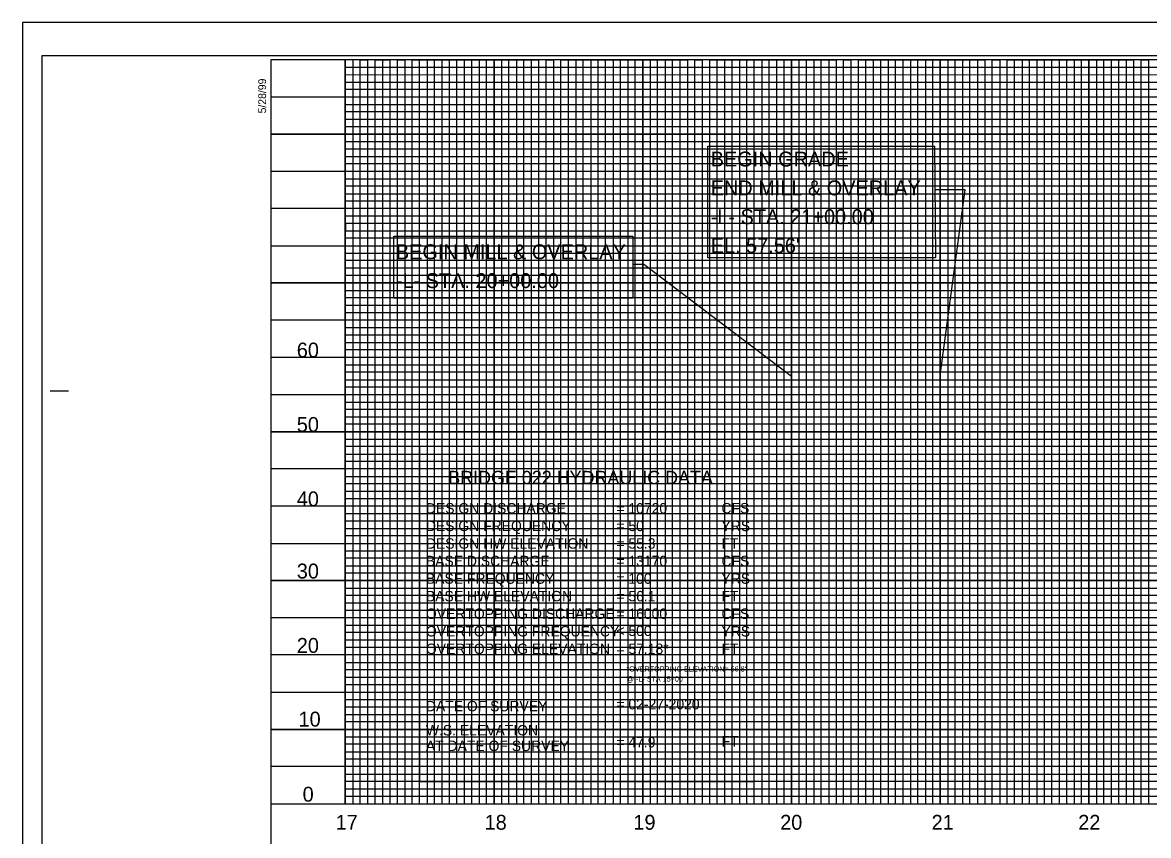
# Model space of a CAD drawing. Extents: x 1019474 to 1021161, y 504129 to 505324.
# Drawn here: x 1019474 to 1020231, y 504683 to 505229 of the extents above; entities that cross this region are included whole.
import ezdxf

# ---------------------------------------------------------------- set-up
doc = ezdxf.new("R2010")
doc.units = 0
for name, color, linetype in [('Exist Vertical Profile Horizontal Axis Label Major', 7, 'Continuous'), ('Exist Vertical Profile Vertical Axis Label', 7, 'Continuous'), ('Prop Grid Mask', 7, 'Continuous'), ('Prop Roadway Bridge', 7, 'Continuous'), ('Prop Vertical Profile Grade Label', 7, 'Continuous'), ('Sheet Cutting Line CELL', 7, 'Continuous'), ('Sheet DOT Grid CELL', 7, 'Continuous'), ('Sheet Layout Profile Border Port 1', 7, 'Continuous'), ('Sheet Plot Border Inside CELL', 7, 'Continuous'), ('Sheet Plot Border Outside CELL', 7, 'Continuous'), ('Sheet Profile CELL', 7, 'Continuous'), ('Sheet Profile Grid Major CELL', 7, 'Continuous'), ('Sheet Profile Grid Middle CELL', 7, 'Continuous'), ('Sheet Profile Grid Minor CELL', 7, 'Continuous')]:
    doc.layers.add(name, color=color, linetype=linetype)

msp = doc.modelspace()

# ---------------------------------------------------------------- linework, layer by layer
at = {"layer": 'Prop Grid Mask'}
for points in [[(1019934.88, 505146.12), (1020087.38, 505146.24), (1020088.08, 505071.15), (1019934.86, 505071.1)], [(1019723.82, 505085.77), (1019884.45, 505085.77), (1019884.45, 505043.97), (1019723.82, 505043.97)], [(1019741.22, 504719.29), (1019966.22, 504719.29), (1019966.22, 504944.29), (1019741.22, 504944.29)]]:
    msp.add_lwpolyline(points, close=True, dxfattribs=at)
at = {"layer": 'Prop Vertical Profile Grade Label'}
for p, q in [((1020107.91, 505116.78), (1020087.38, 505116.78)), ((1020091.22, 504992.18), (1020107.91, 505116.78)), ((1019891.96, 505066.68), (1019884.45, 505066.68)), ((1019991.11, 504991.32), (1019891.96, 505066.68)), ((1019891.96, 505066.68), (1019891.96, 505066.68))]:
    msp.add_line(p, q, dxfattribs=at)
at = {"layer": 'Sheet Cutting Line CELL'}
for p, q in [((1021158.22, 505229.29), (1019474.22, 505229.29)), ((1019474.22, 505229.29), (1019474.22, 504129.29))]:
    msp.add_line(p, q, dxfattribs=at)
at = {"layer": 'Sheet DOT Grid CELL'}
for p, q in [((1019691.22, 504704.29), (1019691.22, 505204.29)), ((1019741.22, 504704.29), (1019741.22, 505204.29)), ((1019791.22, 504704.29), (1019791.22, 505204.29)), ((1019841.22, 504704.29), (1019841.22, 505204.29)), ((1019891.22, 504704.29), (1019891.22, 505204.29)), ((1019941.22, 504704.29), (1019941.22, 505204.29)), ((1019991.22, 504704.29), (1019991.22, 505204.29)), ((1020041.22, 504704.29), (1020041.22, 505204.29)), ((1020091.22, 504704.29), (1020091.22, 505204.29)), ((1020141.22, 504704.29), (1020141.22, 505204.29)), ((1020191.22, 504704.29), (1020191.22, 505204.29)), ((1020941.17, 505154.29), (1019641.22, 505154.29)), ((1020941.17, 505104.29), (1019641.22, 505104.29)), ((1020941.22, 505054.29), (1019641.22, 505054.29)), ((1021141.22, 505004.29), (1019641.22, 505004.29)), ((1021141.22, 504954.29), (1019641.22, 504954.29)), ((1021141.22, 504904.29), (1019641.22, 504904.29)), ((1021141.22, 504854.29), (1019641.22, 504854.29)), ((1021141.22, 504804.29), (1019641.22, 504804.29)), ((1021141.22, 504754.29), (1019641.22, 504754.29))]:
    msp.add_line(p, q, dxfattribs=at)
at = {"layer": 'Sheet Layout Profile Border Port 1'}
msp.add_lwpolyline([(1019691.22, 505043.24), (1019691.22, 504704.29), (1021091.22, 504704.29), (1021091.22, 505043.24)], dxfattribs=at)
at = {"layer": 'Sheet Plot Border Inside CELL'}
msp.add_lwpolyline([(1019487.22, 504151.74), (1021153.72, 504151.74), (1021153.72, 505206.84), (1019487.22, 505206.84)], close=True, dxfattribs=at)
at = {"layer": 'Sheet Plot Border Outside CELL'}
msp.add_lwpolyline([(1019474.22, 504129.29), (1021158.22, 504129.29), (1021158.22, 505229.29), (1019474.22, 505229.29)], close=True, dxfattribs=at)
at = {"layer": 'Sheet Profile CELL'}
for p, q in [((1019492.72, 504981.79), (1019505.22, 504981.79)), ((1019641.22, 504704.29), (1021141.22, 504704.29))]:
    msp.add_line(p, q, dxfattribs=at)
msp.add_lwpolyline([(1021141.22, 505204.29), (1019641.22, 505204.29), (1019641.22, 504154.29), (1021141.22, 504154.29)], close=True, dxfattribs=at)
at = {"layer": 'Sheet Profile Grid Major CELL'}
for points in [[(1019691.22, 505204.29), (1019691.22, 504704.29), (1019741.22, 504704.29), (1019741.22, 505204.29), (1019791.22, 505204.29), (1019791.22, 504704.29), (1019841.22, 504704.29), (1019841.22, 505204.29), (1019891.22, 505204.29), (1019891.22, 504704.29), (1019941.22, 504704.29), (1019941.22, 505204.29), (1019991.22, 505204.29), (1019991.22, 504704.29), (1020041.22, 504704.29), (1020041.22, 505204.29), (1020091.22, 505204.29), (1020091.22, 504704.29), (1020141.22, 504704.29), (1020141.22, 505204.29), (1020191.22, 505204.29), (1020191.22, 504704.29), (1020241.22, 504704.29)], [(1019641.22, 505154.29), (1020941.22, 505154.29)], [(1020941.22, 505104.29), (1019641.22, 505104.29), (1019641.22, 505054.29), (1020941.22, 505054.29)], [(1021141.22, 505004.29), (1019641.22, 505004.29), (1019641.22, 504954.29), (1021141.22, 504954.29)], [(1021141.22, 504904.29), (1019641.22, 504904.29), (1019641.22, 504854.29), (1021141.22, 504854.29)], [(1021141.22, 504804.29), (1019641.22, 504804.29), (1019641.22, 504804.29), (1019641.22, 504754.29), (1021141.22, 504754.29)]]:
    msp.add_lwpolyline(points, dxfattribs=at)
at = {"layer": 'Sheet Profile Grid Middle CELL'}
msp.add_line((1019641.22, 505179.29), (1020941.17, 505179.29), dxfattribs=at)
for points in [[(1019716.22, 505204.29), (1019716.22, 504704.29), (1019766.22, 504704.29), (1019766.22, 505204.29), (1019816.22, 505204.29), (1019816.22, 504704.29), (1019866.22, 504704.29), (1019866.22, 505204.29), (1019916.22, 505204.29), (1019916.22, 504704.29), (1019966.22, 504704.29), (1019966.22, 505204.29), (1020016.22, 505204.29), (1020016.22, 504704.29), (1020066.22, 504704.29), (1020066.22, 505204.29), (1020116.22, 505204.29), (1020116.22, 504704.29), (1020166.22, 504704.29), (1020166.22, 505204.29), (1020216.22, 505204.29), (1020216.22, 504704.29), (1020266.22, 504704.29)], [(1020941.22, 505129.29), (1019641.22, 505129.29), (1019641.22, 505079.29), (1020941.22, 505079.29)], [(1021141.22, 505029.29), (1019641.22, 505029.29), (1019641.22, 504979.29), (1020966.22, 504979.29)], [(1021141.22, 504929.29), (1019641.22, 504929.29), (1019641.22, 504879.29), (1021141.22, 504879.29)], [(1021141.22, 504829.29), (1019641.22, 504829.29), (1019641.22, 504779.29), (1021141.22, 504779.29)], [(1021141.22, 504729.29), (1019641.22, 504729.29)]]:
    msp.add_lwpolyline(points, dxfattribs=at)
at = {"layer": 'Sheet Profile Grid Minor CELL'}
for p, q in [((1019691.22, 505199.29), (1020941.22, 505199.29)), ((1019691.22, 505194.29), (1019691.22, 505194.29)), ((1020941.22, 505194.29), (1019691.22, 505193.94)), ((1019691.22, 505189.29), (1020941.22, 505189.29)), ((1020941.17, 505069.29), (1019691.22, 505069.29)), ((1020941.22, 505064.29), (1019691.22, 505064.29)), ((1020941.22, 505059.29), (1019691.22, 505059.29)), ((1019691.22, 505049.29), (1020941.22, 505049.29)), ((1020941.22, 505044.29), (1019691.22, 505044.29)), ((1019691.22, 505039.29), (1021091.22, 505039.29)), ((1021091.22, 505019.29), (1019691.22, 505019.29)), ((1019691.22, 505014.29), (1021091.22, 505014.29)), ((1021091.22, 504994.29), (1019691.22, 504994.29)), ((1019691.22, 504989.29), (1021091.22, 504989.29)), ((1021091.22, 504969.29), (1019691.22, 504969.29)), ((1019691.22, 504964.29), (1021091.22, 504964.29)), ((1021091.22, 504959.29), (1019691.22, 504959.29)), ((1019691.22, 504949.29), (1021091.22, 504949.29)), ((1021091.22, 504944.29), (1019691.22, 504944.29)), ((1019691.22, 504939.29), (1021091.22, 504939.29)), ((1021091.22, 504934.29), (1019691.22, 504934.29)), ((1019691.22, 504924.29), (1021091.22, 504924.29)), ((1021091.22, 504919.29), (1019691.22, 504919.29)), ((1019691.22, 504914.29), (1021091.22, 504914.29)), ((1021091.22, 504909.29), (1019691.22, 504909.29)), ((1019691.22, 504899.29), (1021091.22, 504899.29)), ((1021091.22, 504894.29), (1019691.22, 504894.29)), ((1019691.22, 504889.29), (1021091.22, 504889.29)), ((1021091.22, 504884.29), (1019691.22, 504884.29)), ((1019691.22, 504874.29), (1021091.22, 504874.29)), ((1021091.22, 504869.29), (1019691.22, 504869.29)), ((1019691.22, 504864.29), (1021091.22, 504864.29)), ((1021091.22, 504859.29), (1019691.22, 504859.29)), ((1019691.22, 504849.29), (1021091.22, 504849.29)), ((1021091.22, 504844.29), (1019691.22, 504844.29)), ((1019691.22, 504839.29), (1021091.22, 504839.29)), ((1021091.22, 504834.29), (1019691.22, 504834.29)), ((1019691.22, 504824.29), (1021091.22, 504824.29)), ((1021091.22, 504819.29), (1019691.22, 504819.29)), ((1021091.22, 504814.29), (1019691.22, 504814.29)), ((1021091.22, 504809.29), (1019691.22, 504809.29)), ((1019691.22, 504799.29), (1021091.22, 504799.29)), ((1021091.22, 504794.29), (1019691.22, 504794.29)), ((1019691.22, 504789.29), (1021091.22, 504789.29)), ((1021091.22, 504784.29), (1019691.22, 504784.29)), ((1019691.22, 504774.29), (1021091.22, 504774.29)), ((1021091.22, 504769.29), (1019691.22, 504769.29)), ((1019691.22, 504764.29), (1021091.22, 504764.29)), ((1021091.22, 504759.29), (1019691.22, 504759.29)), ((1019691.22, 504749.29), (1021091.22, 504749.29)), ((1021091.22, 504744.29), (1019691.22, 504744.29)), ((1019691.22, 504739.29), (1021091.22, 504739.29)), ((1021091.22, 504734.29), (1019691.22, 504734.29)), ((1019691.22, 504724.29), (1021091.22, 504724.29)), ((1021091.22, 504719.29), (1019691.22, 504719.29)), ((1019691.22, 504714.29), (1021091.22, 504714.29))]:
    msp.add_line(p, q, dxfattribs=at)
for points in [[(1019696.22, 505204.29), (1019696.22, 504704.29), (1019701.22, 504704.29), (1019701.22, 505204.29), (1019706.22, 505204.29), (1019706.22, 504704.29), (1019711.22, 504704.29), (1019711.22, 505204.29), (1019721.22, 505204.29), (1019721.22, 504704.29), (1019726.22, 504704.29), (1019726.22, 505204.29), (1019731.22, 505204.29), (1019731.22, 504704.29), (1019736.22, 504704.29), (1019746.22, 504704.29), (1019751.22, 504704.29), (1019751.22, 505204.29), (1019756.22, 505204.29), (1019756.22, 504704.29), (1019761.22, 504704.29), (1019761.22, 505204.29), (1019771.22, 505204.29), (1019771.22, 504704.29), (1019776.22, 504704.29), (1019776.22, 505204.29), (1019781.22, 505204.29), (1019781.22, 504704.29), (1019786.22, 504704.29), (1019786.22, 505204.29), (1019796.22, 505204.29), (1019796.22, 504704.29), (1019801.22, 504704.29), (1019801.22, 505204.29), (1019806.22, 505204.29), (1019806.22, 504704.29), (1019811.22, 504704.29), (1019811.22, 505204.29), (1019821.22, 505204.29), (1019821.22, 504704.29), (1019826.22, 504704.29), (1019826.22, 505204.29), (1019831.22, 505204.29), (1019831.22, 504704.29), (1019836.22, 504704.29), (1019836.22, 505204.29), (1019846.22, 505204.29), (1019846.22, 504704.29), (1019851.22, 504704.29), (1019851.22, 505204.29), (1019856.22, 505204.29), (1019856.22, 504704.29), (1019861.22, 504704.29), (1019861.22, 505204.29), (1019871.22, 505204.29), (1019871.22, 504704.29), (1019876.22, 504704.29), (1019876.22, 505204.29), (1019881.22, 505204.29), (1019881.22, 504704.29), (1019886.22, 504704.29), (1019886.22, 505204.29), (1019896.22, 505204.29), (1019896.22, 504704.29), (1019901.22, 504704.29), (1019901.22, 505204.29), (1019906.22, 505204.29), (1019906.22, 504704.29)], [(1019736.22, 504704.29), (1019736.22, 505204.29), (1019746.22, 505204.29), (1019746.22, 504704.29)], [(1019906.22, 504704.29), (1019911.22, 504704.29), (1019911.22, 505204.29), (1019921.22, 505204.29), (1019921.22, 504704.29), (1019926.22, 504704.29), (1019926.22, 505204.29), (1019931.22, 505204.29), (1019931.22, 504704.29), (1019936.22, 504704.29), (1019936.22, 505204.29), (1019946.22, 505204.29), (1019946.22, 504704.29), (1019951.22, 504704.29), (1019951.22, 505204.29), (1019956.22, 505204.29), (1019956.22, 504704.29), (1019961.22, 504704.29), (1019961.22, 505204.29), (1019971.22, 505204.29), (1019971.22, 504704.29), (1019976.22, 504704.29), (1019976.22, 505204.29), (1019981.22, 505204.29), (1019981.22, 504704.29), (1019986.22, 504704.29), (1019986.22, 505204.29), (1019996.22, 505204.29), (1019996.22, 504704.29), (1020001.22, 504704.29), (1020001.22, 505204.29), (1020006.22, 505204.29), (1020006.22, 504704.29), (1020011.22, 504704.29), (1020011.22, 505204.29), (1020021.22, 505204.29), (1020021.22, 504704.29), (1020026.22, 504704.29), (1020026.22, 505204.29), (1020031.22, 505204.29), (1020031.22, 504704.29), (1020036.22, 504704.29), (1020036.22, 505204.29), (1020046.22, 505204.29), (1020046.22, 504704.29), (1020051.22, 504704.29), (1020051.22, 505204.29), (1020056.22, 505204.29), (1020056.22, 504704.29), (1020061.22, 504704.29), (1020061.22, 505204.29), (1020071.22, 505204.29), (1020071.22, 504704.29), (1020076.22, 504704.29), (1020076.22, 505204.29), (1020081.22, 505204.29), (1020081.22, 504704.29), (1020086.22, 504704.29), (1020086.22, 505204.29), (1020096.22, 505204.29), (1020096.22, 504704.29), (1020101.22, 504704.29), (1020101.22, 505204.29), (1020106.22, 505204.29), (1020106.22, 504704.29), (1020111.22, 504704.29), (1020111.22, 505204.29), (1020121.22, 505204.29), (1020121.22, 504704.29), (1020126.22, 504704.29), (1020126.22, 505204.29), (1020131.22, 505204.29), (1020131.22, 504704.29), (1020136.22, 504704.29), (1020136.22, 505204.29), (1020146.22, 505204.29), (1020146.22, 504704.29), (1020151.22, 504704.29), (1020151.22, 505204.29), (1020156.22, 505204.29), (1020156.22, 504704.29), (1020161.22, 504704.29), (1020161.22, 505204.29), (1020171.22, 505204.29), (1020171.22, 504704.29), (1020176.22, 504704.29), (1020176.22, 505204.29), (1020181.22, 505204.29), (1020181.22, 504704.29), (1020186.22, 504704.29), (1020186.22, 505204.29), (1020196.22, 505204.29), (1020196.22, 504704.29), (1020201.22, 504704.29), (1020201.22, 505204.29), (1020206.22, 505204.29), (1020206.22, 504704.29), (1020211.22, 504704.29), (1020211.22, 505204.29), (1020221.22, 505204.29)], [(1020221.22, 505204.29), (1020221.22, 504704.29), (1020226.22, 504704.29), (1020226.22, 505204.29), (1020231.22, 505204.29), (1020231.22, 504704.29), (1020236.22, 504704.29)], [(1020941.22, 505184.29), (1019691.22, 505184.29), (1019691.22, 505174.29), (1020941.22, 505174.29)], [(1020941.17, 505169.29), (1019691.22, 505169.29), (1019691.22, 505164.29), (1020941.22, 505164.29)], [(1020941.22, 505159.29), (1019691.22, 505159.29), (1019691.22, 505149.29), (1020941.22, 505149.29)], [(1020941.22, 505144.29), (1019691.22, 505144.29), (1019691.22, 505139.29), (1020941.22, 505139.29)], [(1020941.22, 505134.29), (1019691.22, 505134.29), (1019691.22, 505124.29), (1020941.22, 505124.29)], [(1020941.22, 505119.29), (1019691.22, 505119.29), (1019691.22, 505114.29), (1020941.22, 505114.29)], [(1020941.22, 505109.29), (1019691.22, 505109.29), (1019691.22, 505099.29), (1020941.22, 505099.29)], [(1020941.22, 505094.19), (1019691.32, 505094.19), (1019691.32, 505089.29), (1020941.22, 505089.29)], [(1020941.22, 505084.29), (1019691.22, 505084.29), (1019691.22, 505074.29), (1020941.22, 505074.29)], [(1021091.22, 505034.29), (1019691.22, 505034.29), (1019691.22, 505024.29), (1021091.22, 505024.29)], [(1021091.22, 505009.29), (1019691.22, 505009.29), (1019691.22, 504999.29), (1021091.22, 504999.29)], [(1021091.22, 504984.29), (1019691.22, 504984.29), (1019691.22, 504974.29), (1021091.22, 504974.29)], [(1021091.22, 504709.29), (1019691.22, 504709.29)]]:
    msp.add_lwpolyline(points, dxfattribs=at)

# ---------------------------------------------------------------- texts
at = {"layer": 'Exist Vertical Profile Horizontal Axis Label Major'}
for s, p in [('17', (1019684.76, 504686.86)), ('18', (1019784.89, 504686.86)), ('19', (1019884.93, 504686.86)), ('20', (1019983.61, 504686.86)), ('21', (1020085.45, 504686.86)), ('22', (1020184, 504686.86))]:
    msp.add_text(s, height=10, dxfattribs=at).set_placement(p)
at = {"layer": 'Exist Vertical Profile Vertical Axis Label'}
for s, p in [('60', (1019658.61, 505004.19)), ('50', (1019658.61, 504954.19)), ('40', (1019658.61, 504904.19)), ('30', (1019658.61, 504855.7)), ('20', (1019658.61, 504805.71)), ('10', (1019659.8, 504756.19)), ('0', (1019662.56, 504705.73))]:
    msp.add_text(s, height=10, dxfattribs=at).set_placement(p)
at = {"layer": 'Prop Roadway Bridge'}
for s, height, p in [('BRIDGE 022 HYDRAULIC DATA', 9, (1019760.45, 504919.04)), ('DESIGN DISCHARGE', 7, (1019745.42, 504899.34)), ('= 10720', 7, (1019873.49, 504899.34)), ('CFS', 7, (1019944.14, 504899.44)), ('DESIGN FREQUENCY', 7, (1019745.42, 504887.54)), ('= 50', 7, (1019873.49, 504887.54)), ('YRS', 7, (1019944.14, 504887.54)), ('DESIGN HW ELEVATION', 7, (1019745.42, 504875.74)), ('= 55.3', 7, (1019873.49, 504875.74)), ('FT', 7, (1019944.14, 504875.74)), ('BASE DISCHARGE', 7, (1019745.42, 504863.94)), ('= 13170', 7, (1019873.49, 504863.94)), ('CFS', 7, (1019944.14, 504863.94)), ('BASE FREQUENCY', 7, (1019745.42, 504852.14)), ('= 100', 7, (1019873.49, 504852.14)), ('YRS', 7, (1019944.14, 504852.14)), ('BASE HW ELEVATION', 7, (1019745.42, 504840.34)), ('= 56.1', 7, (1019873.49, 504840.34)), ('FT', 7, (1019944.14, 504840.34)), ('OVERTOPPING DISCHARGE', 7, (1019745.42, 504828.54)), ('= 16000', 7, (1019873.49, 504828.54)), ('CFS', 7, (1019944.14, 504828.54)), ('OVERTOPPING FREQUENCY', 7, (1019745.42, 504816.74)), ('< 500', 7, (1019873.49, 504817.04)), ('YRS', 7, (1019944.14, 504816.74)), ('OVERTOPPING ELEVATION', 7, (1019745.42, 504804.94)), ('= 57.18*', 7, (1019873.49, 504804.94)), ('FT', 7, (1019944.14, 504804.94)), ("*OVERTOPPING ELEVATION= 56.8'", 3.5, (1019880.34, 504793.19)), ('@ -L- STA 15+00', 3.5, (1019880.34, 504786.41)), ('DATE OF SURVEY', 7, (1019745.42, 504766.44)), ('= 02-27-2020', 7, (1019873.49, 504767.74)), ('W.S. ELEVATION', 7, (1019745.42, 504750.24)), ('AT DATE OF SURVEY', 7, (1019745.42, 504739.74)), ('= 47.9', 7, (1019873.49, 504742.19)), ('FT', 7, (1019944.14, 504742.79))]:
    msp.add_text(s, height=height, dxfattribs=at).set_placement(p)
at = {"layer": 'Prop Vertical Profile Grade Label'}
for s, p in [('BEGIN GRADE', (1019936.9, 505132.55)), ('END MILL & OVERLAY', (1019936.9, 505113.17)), ('-L- STA. 21+00.00', (1019936.9, 505093.8)), ('BEGIN MILL & OVERLAY', (1019725.26, 505070.24)), ("EL. 57.56'", (1019936.9, 505074.42)), ('-L- STA. 20+00.00', (1019725.26, 505050.86))]:
    msp.add_text(s, height=10, dxfattribs=at).set_placement(p)
at = {"layer": 'Sheet Profile CELL'}
msp.add_text('5/28/99', height=5.25, rotation=90, dxfattribs=at).set_placement((1019637.98, 505168.21))

doc.saveas('drawing.dxf')
